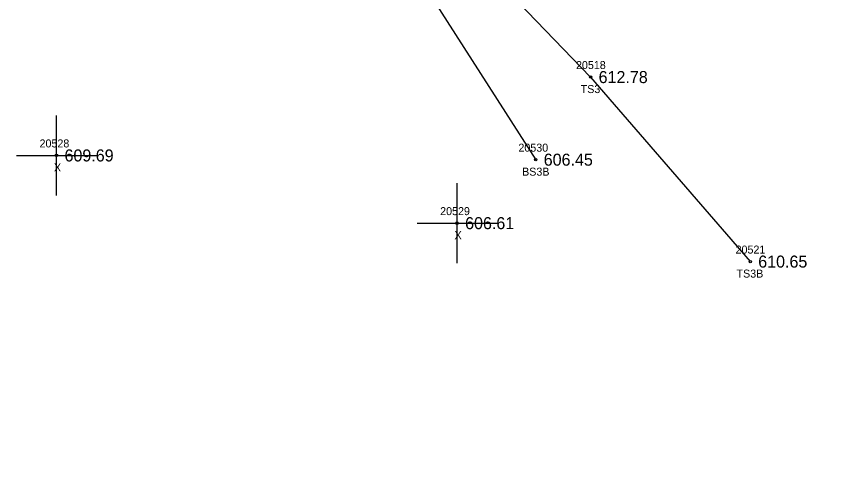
# Model space of a CAD drawing. Extents: x 1530159 to 1531652, y 877045 to 877724.
# Drawn here: x 1530286.1 to 1530389, y 877217.4 to 877274.6 of the extents above; entities that cross this region are included whole.
import ezdxf

# ---------------------------------------------------------------- set-up
doc = ezdxf.new("R2010")
doc.units = 0
for name, color, linetype in [('RD_DTM_BkLn2', 7, 'Continuous'), ('RD_DTM_BkLn_txCode', 7, 'Continuous'), ('RD_EX_Misc', 7, 'Continuous'), ('RD_EX_Misc_txCode', 7, 'Continuous'), ('RD_EX_TX_Misc_ELEV', 7, 'Continuous'), ('RD_SMD_Locator', 7, 'Continuous')]:
    doc.layers.add(name, color=color, linetype=linetype)

msp = doc.modelspace()

# ---------------------------------------------------------------- linework, layer by layer
at = {"layer": 'RD_DTM_BkLn2'}
for points in [[(1530327.83, 877302.7), (1530336.11, 877279.98), (1530350.95, 877256.76)], [(1530781.59, 877237.74), (1530769.19, 877234.54), (1530707.91, 877235.08), (1530658.9, 877217.43), (1530601.44, 877222.78), (1530585.47, 877250.74), (1530554.71, 877252.85), (1530502.71, 877258.91), (1530451.66, 877269.63), (1530401.38, 877279.82), (1530344.51, 877291.95), (1530339.77, 877285.8), (1530357.81, 877267.08), (1530377.75, 877244.03)]]:
    msp.add_lwpolyline(points, dxfattribs=at)
at = {"layer": 'RD_EX_Misc'}
for p, q in [((1530291.08, 877252.29), (1530291.08, 877262.29)), ((1530286.08, 877257.29), (1530296.08, 877257.29)), ((1530341.13, 877243.83), (1530341.13, 877253.83)), ((1530336.13, 877248.83), (1530346.13, 877248.83))]:
    msp.add_line(p, q, dxfattribs=at)
at = {"layer": 'RD_SMD_Locator'}
for centre in [(1530357.81, 877267.08), (1530291.08, 877257.29), (1530350.95, 877256.76), (1530341.13, 877248.83), (1530377.75, 877244.03)]:
    msp.add_circle(centre, 0.15, dxfattribs=at)

# ---------------------------------------------------------------- texts
at = {"layer": 'RD_DTM_BkLn_txCode'}
for s, p in [('20518', (1530355.98, 877268.08)), ('TS3', (1530356.57, 877265.08)), ('20530', (1530348.79, 877257.76)), ('BS3B', (1530349.25, 877254.76)), ('20521', (1530375.92, 877245.03)), ('TS3B', (1530376.04, 877242.03))]:
    msp.add_text(s, height=1, dxfattribs=at).set_placement(p)
at = {"layer": 'RD_EX_Misc_txCode'}
for s, p in [('20528', (1530288.96, 877258.29)), ('X', (1530290.76, 877255.29)), ('20529', (1530339.01, 877249.83)), ('X', (1530340.81, 877246.83))]:
    msp.add_text(s, height=1, dxfattribs=at).set_placement(p)
at = {"layer": 'RD_EX_TX_Misc_ELEV'}
for s, p in [('612.78', (1530358.81, 877266.33)), ('609.69', (1530292.08, 877256.54)), ('606.45', (1530351.95, 877256.01)), ('606.61', (1530342.13, 877248.08)), ('610.65', (1530378.75, 877243.28))]:
    msp.add_text(s, height=1.5, dxfattribs=at).set_placement(p)

doc.saveas('drawing.dxf')
